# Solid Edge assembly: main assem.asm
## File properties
Author: Vicky Raina
Template: Normal.asm
Last saved by: CADCIM
Revision: 14
Application: Solid Edge
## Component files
master rod.par
piston.par
piston pin.par
arti subassm.asm
piston pin plug.par
piston ring.par
master rod bearing.par
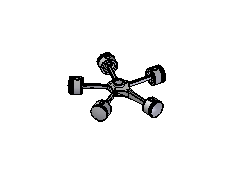
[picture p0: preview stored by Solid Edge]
